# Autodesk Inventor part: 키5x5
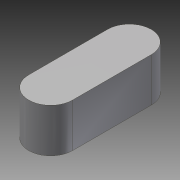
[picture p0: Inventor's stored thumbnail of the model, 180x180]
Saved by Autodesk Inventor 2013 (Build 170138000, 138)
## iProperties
Created: 2011-12
Part Number: 키5x5
Document SubType Name: Modeling
Designer: KYOUNG IL JANG
Density: 7.86 g/cm^3
Material: 강, 연강
Mass: 2.54015 g
Surface Area: 2.9781 cm^2
Volume: 0.323175 cm^3
Author: 석형태
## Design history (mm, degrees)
sketch "스케치1"
  geometry: L1 (34.626, -76.005)-(34.626, -85.005); L2 (39.626, -76.005)-(39.626, -85.005); A1 r 2.5 centre (37.126, -85.005) between (34.626, -85.005) and (39.626, -85.005); A2 r 2.5 centre (37.126, -76.005) between (39.626, -76.005) and (34.626, -76.005); 3 further points
  constraints: 6 point on circle, 4 end point, 4 tangent, 2 centre point, 1 equal radius, 1 vertical alignment
  dimensions: "d0" = 5 diameter of A2; "d1" = 14 distance of point (37.126, -87.505) point (37.126, -73.505)
extrude "돌출1" new body sketch "스케치1" distance "d4" = 5; taper "d5" = 0 deg
node "솔리드1"
